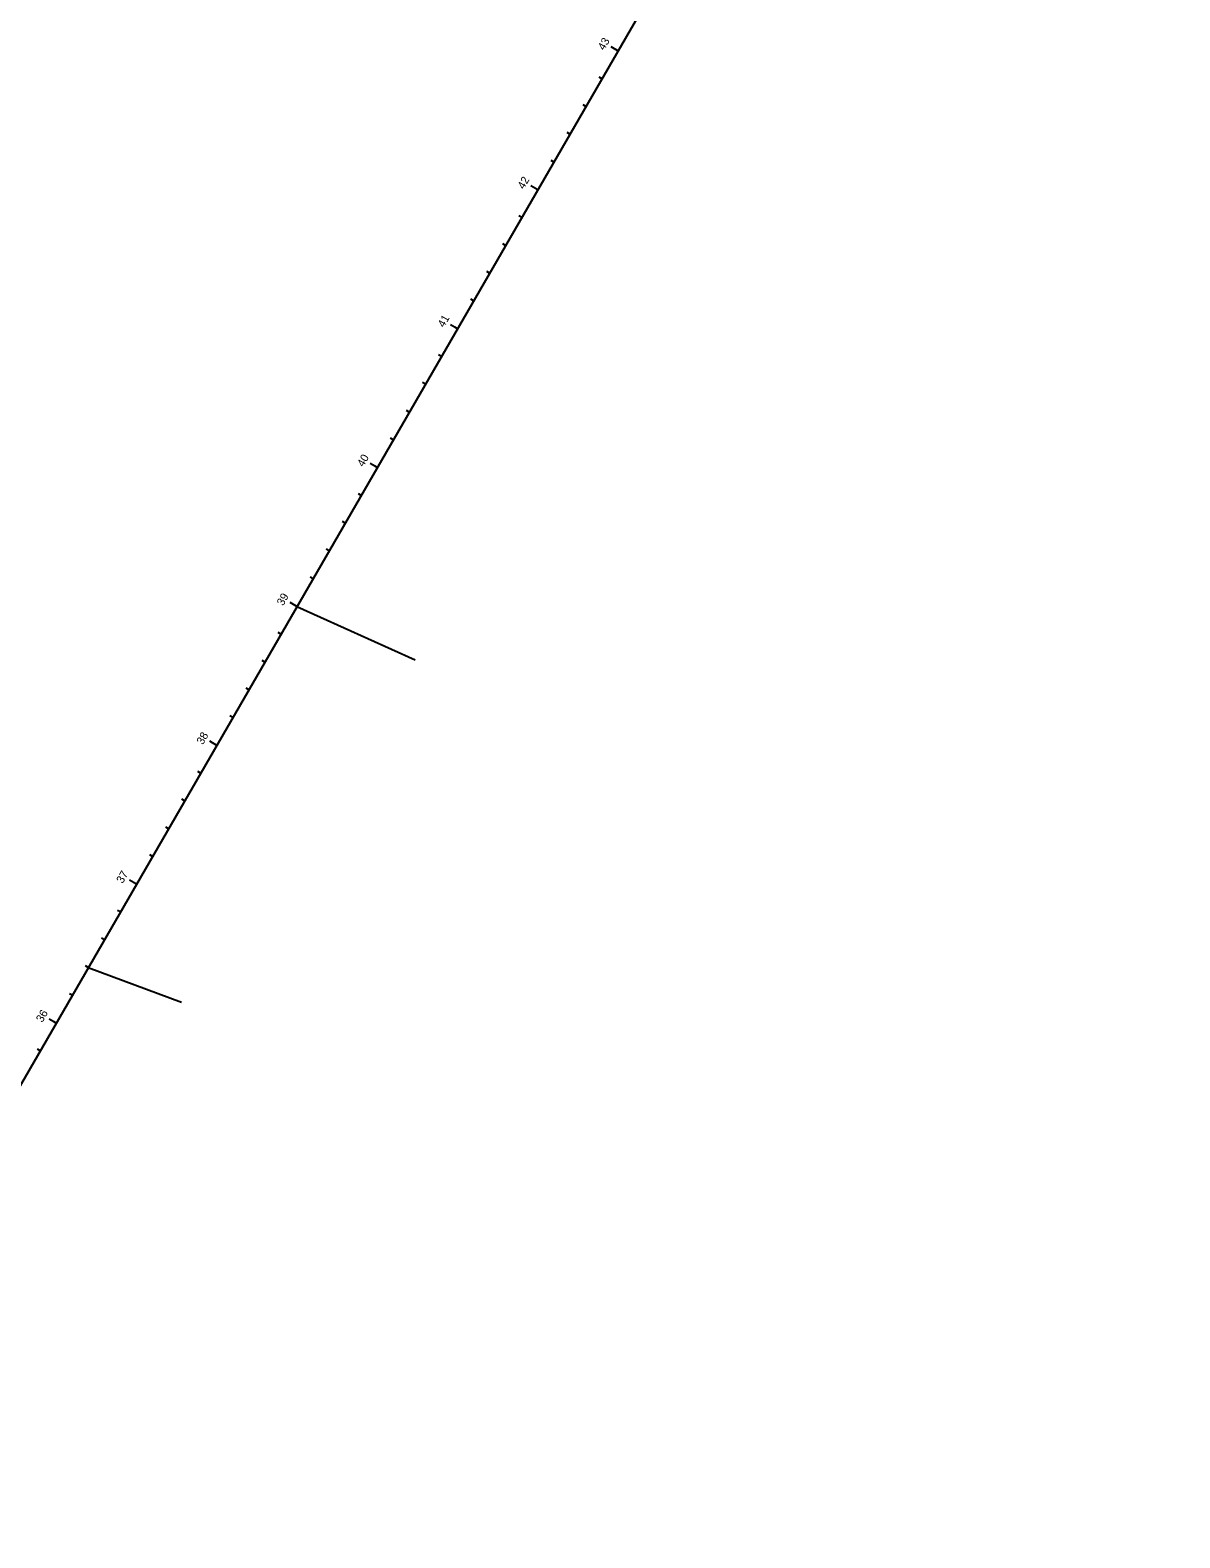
# Model space of a CAD drawing. Extents: x 2003883 to 2007688, y 399149 to 412300.
# Drawn here: x 2006971 to 2007688, y 402588 to 403528 of the extents above; entities that cross this region are included whole.
import ezdxf

# ---------------------------------------------------------------- set-up
doc = ezdxf.new("R2010")
doc.units = 0
for name, color, linetype in [('BaselineSurvey', 7, 'Continuous'), ('CLConst_dp', 7, 'Continuous'), ('TextAlgnStation100', 7, 'Continuous'), ('TextAlgnStation1000', 7, 'Continuous'), ('TextAlgnStation500', 7, 'Continuous'), ('TextAlgnTicks100', 7, 'Continuous'), ('TextAlgnTicks1000', 7, 'Continuous'), ('TextAlgnTicks500', 7, 'Continuous'), ('TextAlgnTicks5000', 7, 'Continuous')]:
    doc.layers.add(name, color=color, linetype=linetype)

msp = doc.modelspace()

# ---------------------------------------------------------------- linework, layer by layer
at = {"layer": 'BaselineSurvey'}
msp.add_lwpolyline([(2006095.1, 401364.22), (2006751.44, 402500.64), (2007687.69, 404121.69)], dxfattribs=at)
at = {"layer": 'CLConst_dp'}
for p, q in [((2007137.54, 403169.14), (2007211.11, 403135.84)), ((2007007.51, 402944), (2007065.68, 402922.33))]:
    msp.add_line(p, q, dxfattribs=at)
at = {"layer": 'TextAlgnTicks100'}
for p, q in [((2007337.59, 403515.52), (2007333.27, 403518.02)), ((2007327.59, 403498.2), (2007325.86, 403499.2)), ((2007317.59, 403480.89), (2007315.86, 403481.89)), ((2007307.59, 403463.57), (2007305.85, 403464.57)), ((2007297.58, 403446.25), (2007295.85, 403447.25)), ((2007287.58, 403428.93), (2007283.25, 403431.43)), ((2007277.58, 403411.61), (2007275.85, 403412.61)), ((2007267.58, 403394.29), (2007265.84, 403395.29)), ((2007257.57, 403376.97), (2007255.84, 403377.97)), ((2007247.57, 403359.65), (2007245.84, 403360.65)), ((2007237.57, 403342.33), (2007233.24, 403344.83)), ((2007227.57, 403325.02), (2007225.83, 403326.02)), ((2007217.56, 403307.7), (2007215.83, 403308.7)), ((2007207.56, 403290.38), (2007205.83, 403291.38)), ((2007197.56, 403273.06), (2007195.83, 403274.06)), ((2007187.55, 403255.74), (2007183.22, 403258.24)), ((2007177.55, 403238.42), (2007175.82, 403239.42)), ((2007167.55, 403221.1), (2007165.82, 403222.1)), ((2007157.55, 403203.78), (2007155.81, 403204.78)), ((2007147.54, 403186.46), (2007145.81, 403187.46)), ((2007137.54, 403169.14), (2007133.21, 403171.65)), ((2007127.54, 403151.83), (2007125.81, 403152.83)), ((2007117.54, 403134.51), (2007115.8, 403135.51)), ((2007107.53, 403117.19), (2007105.8, 403118.19)), ((2007097.53, 403099.87), (2007095.8, 403100.87)), ((2007087.53, 403082.55), (2007083.2, 403085.05)), ((2007077.52, 403065.23), (2007075.79, 403066.23)), ((2007067.52, 403047.91), (2007065.79, 403048.91)), ((2007057.52, 403030.59), (2007055.79, 403031.59)), ((2007047.52, 403013.27), (2007045.79, 403014.27)), ((2007037.51, 402995.96), (2007033.18, 402998.46)), ((2007027.51, 402978.64), (2007025.78, 402979.64)), ((2007017.51, 402961.32), (2007015.78, 402962.32)), ((2007007.51, 402944), (2007005.77, 402945)), ((2006997.5, 402926.68), (2006995.77, 402927.68)), ((2006987.5, 402909.36), (2006983.17, 402911.86)), ((2006977.5, 402892.04), (2006975.77, 402893.04))]:
    msp.add_line(p, q, dxfattribs=at)
at = {"layer": 'TextAlgnTicks1000'}
for p, q in [((2007287.58, 403428.93), (2007285.85, 403429.93)), ((2007187.55, 403255.74), (2007183.22, 403258.24)), ((2007087.53, 403082.55), (2007085.8, 403083.55)), ((2006987.5, 402909.36), (2006985.77, 402910.36))]:
    msp.add_line(p, q, dxfattribs=at)
at = {"layer": 'TextAlgnTicks500'}
for p, q in [((2007337.59, 403515.52), (2007335.86, 403516.52)), ((2007287.58, 403428.93), (2007285.85, 403429.93)), ((2007237.57, 403342.33), (2007235.84, 403343.33)), ((2007187.55, 403255.74), (2007183.22, 403258.24)), ((2007137.54, 403169.14), (2007135.81, 403170.14)), ((2007087.53, 403082.55), (2007085.8, 403083.55)), ((2007037.51, 402995.96), (2007035.78, 402996.96)), ((2006987.5, 402909.36), (2006985.77, 402910.36))]:
    msp.add_line(p, q, dxfattribs=at)
at = {"layer": 'TextAlgnTicks5000'}
msp.add_line((2007187.55, 403255.74), (2007185.82, 403256.74), dxfattribs=at)

# ---------------------------------------------------------------- texts
at = {"layer": 'TextAlgnStation100'}
for s, p in [('43', (2007328.94, 403515.53)), ('42', (2007278.92, 403428.94)), ('41', (2007229.14, 403342.73)), ('40', (2007178.93, 403255.8)), ('39', (2007128.91, 403169.2)), ('38', (2007078.88, 403082.57)), ('37', (2007028.91, 402996.06)), ('36', (2006978.87, 402909.41))]:
    msp.add_text(s, height=4.98, rotation=59.99111, dxfattribs=at).set_placement(p)
at = {"layer": 'TextAlgnStation1000'}
msp.add_text('40', height=4.98, rotation=59.99111, dxfattribs=at).set_placement((2007178.93, 403255.8))
at = {"layer": 'TextAlgnStation500'}
msp.add_text('40', height=4.98, rotation=59.99111, dxfattribs=at).set_placement((2007178.93, 403255.8))

doc.saveas('drawing.dxf')
